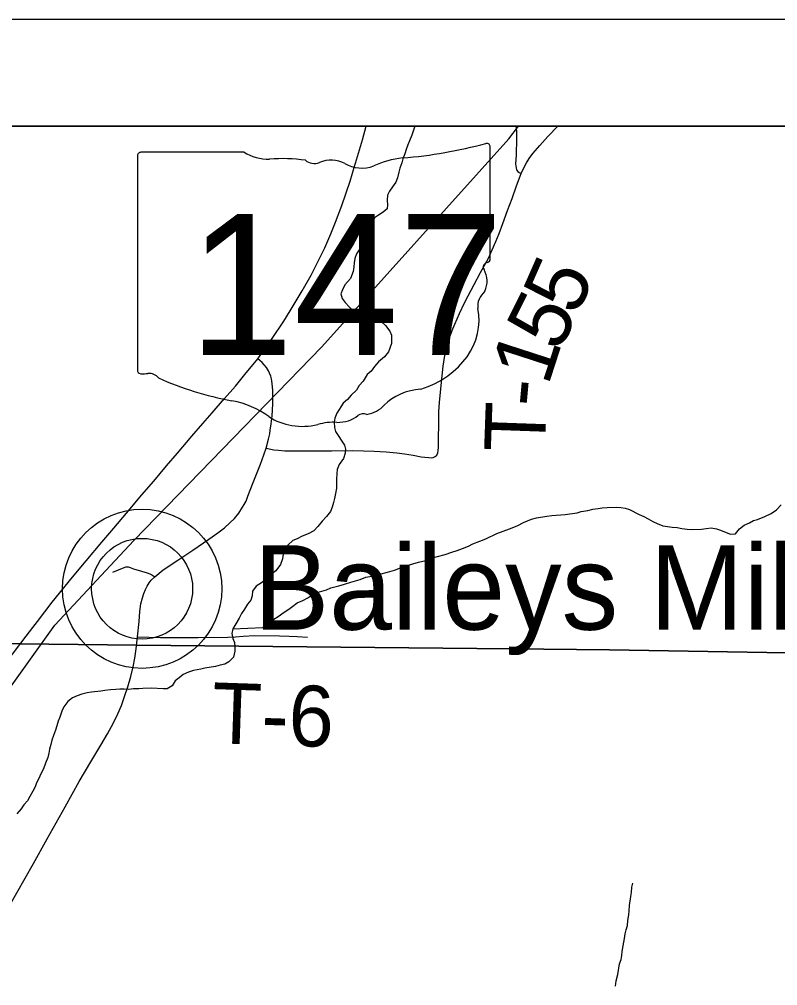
# Model space of a CAD drawing. Extents: x 0 to 34, y 0 to 22.
# Drawn here: x 27.124 to 27.832, y 20.097 to 21 of the extents above; entities that cross this region are included whole.
import ezdxf

# ---------------------------------------------------------------- set-up
doc = ezdxf.new("R2010")
doc.units = 0
for name, color, linetype in [('GM_X_Corporation', 7, 'Continuous'), ('GM_X_Minor_River', 7, 'Continuous'), ('GM_X_Rail_Line', 7, 'Continuous'), ('GM_X_State_Route', 7, 'Continuous'), ('GM_X_State_Shield', 7, 'Continuous'), ('GM_X_Township_Road', 7, 'Continuous'), ('GM_X_Township_Road_Text', 7, 'Continuous'), ('GM_X_Unincorporated', 7, 'Continuous'), ('GM_X_Unincorporated_Location', 7, 'Continuous'), ('GM_X_Unincorporated_Text', 7, 'Continuous'), ('SH_Data', 7, 'Continuous')]:
    doc.layers.add(name, color=color, linetype=linetype)

msp = doc.modelspace()

# ---------------------------------------------------------------- linework, layer by layer
at = {"layer": 'GM_X_Corporation'}
for points in [[(30.31667, 20.9), (27.1022, 20.9), (27.08976, 20.41697), (27.08968, 20.41348), (27.08896, 20.36917), (27.08729, 20.26647), (27.09073, 20.12299), (27.08852, 20.11389), (27.08642, 20.01381), (27.07613, 19.68064), (27.07326, 19.49798), (27.07194, 19.39116), (27.04874, 18.58046), (27.04191, 17.82361), (27.03491, 17.55216), (27.02338, 16.66109), (27.01239, 14.98802), (27.00568, 14.51357), (27.29989, 14.51067), (27.80309, 14.50906), (28.4032, 14.497)], [(29.55027, 20.37882), (27.67509, 20.4106), (27.58291, 20.41163), (27.2336, 20.4152), (27.12389, 20.41631), (27.08976, 20.41697), (27.08968, 20.41348), (27.08896, 20.36917), (27.08729, 20.26647), (27.09073, 20.12299), (27.08852, 20.11389), (27.08642, 20.01381), (27.07613, 19.68064), (27.07326, 19.49798), (27.07194, 19.39116), (27.04874, 18.58046), (27.04191, 17.82361), (27.03491, 17.55216), (27.02338, 16.66109), (27.01239, 14.98802), (27.00568, 14.51357), (27.29989, 14.51067), (27.80309, 14.50906), (28.4032, 14.497)]]:
    msp.add_lwpolyline(points, dxfattribs=at)
msp.add_lwpolyline([(30.31667, 20.36493), (30.31667, 20.9), (27.1022, 20.9), (27.08976, 20.41697), (27.12389, 20.41631), (27.2336, 20.4152), (27.58291, 20.41163), (27.67509, 20.4106), (29.55027, 20.37882)], close=True, dxfattribs=at)
at = {"layer": 'GM_X_Minor_River'}
msp.add_line((27.49339, 20.9), (27.49271, 20.89826), dxfattribs=at)
for points in [[(27.49271, 20.89826), (27.49055, 20.89178), (27.48837, 20.88644), (27.48692, 20.88262), (27.4851, 20.87842), (27.48404, 20.87423), (27.48223, 20.86964), (27.48116, 20.86584), (27.47935, 20.86088), (27.47828, 20.85707), (27.47724, 20.85174), (27.47542, 20.84792), (27.47247, 20.84331), (27.46951, 20.83947), (27.46768, 20.83565), (27.46738, 20.83109), (27.46784, 20.82655), (27.46753, 20.82275), (27.4638, 20.81965), (27.45931, 20.81692), (27.45556, 20.81458), (27.45298, 20.81075), (27.45191, 20.80693), (27.45047, 20.80274), (27.45056, 20.79781), (27.44988, 20.79325), (27.44616, 20.78977), (27.44207, 20.78553), (27.43874, 20.78092), (27.43731, 20.77635), (27.43662, 20.77254), (27.43631, 20.76875), (27.43563, 20.76418), (27.43309, 20.75769), (27.42789, 20.75192), (27.4257, 20.74733), (27.42426, 20.74351), (27.42547, 20.73898), (27.42818, 20.73524), (27.43628, 20.72666), (27.44049, 20.72408), (27.44505, 20.72264), (27.44885, 20.72157), (27.4538, 20.72014), (27.45837, 20.71832), (27.46217, 20.71725), (27.46602, 20.71391), (27.46989, 20.70867), (27.47147, 20.7049), (27.47161, 20.69694), (27.46872, 20.68931), (27.46501, 20.68469), (27.45942, 20.68004), (27.45571, 20.67543), (27.45238, 20.6712), (27.44865, 20.6681), (27.44497, 20.66197), (27.44126, 20.65774), (27.43869, 20.65352), (27.43385, 20.64888), (27.43052, 20.64465), (27.42642, 20.64117), (27.42052, 20.63197), (27.41871, 20.62738), (27.41802, 20.62358), (27.4181, 20.61865), (27.41931, 20.61488), (27.42164, 20.61113), (27.42514, 20.60588), (27.42747, 20.60213), (27.42867, 20.59836), (27.42836, 20.59456), (27.42656, 20.5896), (27.4225, 20.58384), (27.42068, 20.57926), (27.42037, 20.57546), (27.42009, 20.56977), (27.42023, 20.56181), (27.41918, 20.55686), (27.41813, 20.55229), (27.41744, 20.54849), (27.416, 20.54391), (27.41456, 20.5401), (27.41085, 20.53548), (27.40677, 20.53086), (27.40269, 20.52586), (27.39898, 20.522), (27.39373, 20.51925), (27.38809, 20.51688), (27.38322, 20.51452), (27.37946, 20.51294), (27.37461, 20.50868), (27.37205, 20.50408), (27.37022, 20.50026), (27.36954, 20.4957), (27.36774, 20.49036), (27.3633, 20.48459), (27.35845, 20.48071), (27.35473, 20.47686), (27.34988, 20.47336), (27.34501, 20.47024)], [(27.32338, 20.43042), (27.35136, 20.43167), (27.35658, 20.43593), (27.3607, 20.43866), (27.36669, 20.44256), (27.37042, 20.44528), (27.37566, 20.44878), (27.3794, 20.4515), (27.3835, 20.45461), (27.38876, 20.45697), (27.39326, 20.45933), (27.4, 20.46362), (27.40639, 20.46563), (27.41092, 20.46684), (27.41467, 20.46881), (27.4222, 20.47045), (27.42747, 20.47206), (27.43349, 20.47406), (27.44215, 20.47649), (27.44742, 20.47848), (27.45307, 20.47972), (27.45683, 20.48092), (27.46061, 20.48137), (27.46776, 20.48339), (27.47417, 20.48502), (27.4783, 20.48661), (27.48206, 20.48819), (27.4862, 20.4894), (27.49674, 20.49262), (27.50352, 20.49425), (27.50992, 20.49664), (27.51443, 20.49786), (27.52159, 20.49988), (27.52799, 20.50189), (27.53288, 20.50349), (27.53776, 20.50547), (27.54341, 20.50746), (27.54753, 20.50981), (27.55392, 20.5122), (27.55955, 20.51457), (27.57006, 20.51931), (27.5757, 20.52168), (27.58172, 20.52368), (27.58585, 20.52527), (27.58961, 20.52686), (27.59486, 20.5296), (27.60237, 20.53277), (27.60689, 20.53398), (27.6167, 20.53567), (27.62124, 20.53613), (27.63371, 20.53711), (27.64503, 20.53882), (27.64879, 20.54003), (27.65483, 20.54089), (27.65973, 20.54211), (27.66463, 20.54296), (27.66841, 20.54341), (27.67294, 20.54386), (27.68202, 20.54402), (27.68581, 20.54371), (27.68999, 20.54303), (27.69379, 20.54196), (27.70295, 20.53719), (27.70715, 20.53536), (27.71135, 20.53316), (27.71556, 20.53058), (27.71975, 20.52876), (27.72509, 20.52657), (27.72926, 20.52589), (27.73381, 20.52521), (27.73836, 20.52491), (27.74291, 20.52423), (27.74784, 20.52356), (27.75163, 20.52325), (27.76109, 20.52341), (27.76562, 20.52425), (27.77015, 20.52471), (27.77509, 20.52366), (27.77889, 20.52259), (27.78423, 20.52041), (27.78842, 20.51896), (27.79295, 20.51904), (27.79666, 20.52366), (27.80114, 20.52715), (27.80602, 20.52951), (27.80977, 20.53147), (27.81353, 20.53268), (27.82029, 20.53545), (27.8263, 20.53821), (27.83116, 20.54171), (27.83562, 20.54634)], [(27.34501, 20.47024), (27.34169, 20.46563), (27.34139, 20.46107), (27.33994, 20.45726), (27.33698, 20.45341), (27.33403, 20.44881), (27.33146, 20.44459), (27.32926, 20.44038), (27.32595, 20.43502), (27.32338, 20.43042), (27.32233, 20.42585), (27.32316, 20.42132), (27.32474, 20.41755), (27.32519, 20.41339), (27.32526, 20.40959), (27.32384, 20.40388), (27.31938, 20.39963), (27.31563, 20.39729), (27.31149, 20.39646), (27.30697, 20.39524), (27.29716, 20.39355), (27.29339, 20.39273), (27.2866, 20.39147), (27.28171, 20.38987), (27.27683, 20.38751), (27.2731, 20.38441), (27.26936, 20.38169), (27.26642, 20.37709), (27.26192, 20.37435), (27.25814, 20.37428), (27.24716, 20.37485), (27.23921, 20.37471), (27.23544, 20.37427), (27.23052, 20.37418), (27.22599, 20.37372), (27.22182, 20.37403), (27.21766, 20.37396), (27.21388, 20.37351), (27.20896, 20.37342), (27.20368, 20.37257), (27.1999, 20.37213), (27.19122, 20.37122), (27.18707, 20.37039), (27.18217, 20.36916), (27.17766, 20.36757), (27.17352, 20.36598), (27.16904, 20.36249), (27.16535, 20.35749), (27.16353, 20.35329), (27.16173, 20.34794), (27.1599, 20.34412), (27.15885, 20.33955), (27.1574, 20.33573), (27.1556, 20.33077), (27.15416, 20.32619), (27.1531, 20.32238), (27.15204, 20.31781), (27.15135, 20.31401), (27.15028, 20.3102), (27.1481, 20.30485), (27.14631, 20.29951), (27.14374, 20.29491), (27.14192, 20.29033), (27.13972, 20.2865), (27.13865, 20.28269), (27.13646, 20.27847), (27.13352, 20.27349), (27.13131, 20.26966), (27.12798, 20.26581), (27.12539, 20.26197), (27.12131, 20.25735)], [(27.68078, 20.09646), (27.68145, 20.1014), (27.68286, 20.10712), (27.68457, 20.11739), (27.68602, 20.12121), (27.68671, 20.12501), (27.68702, 20.12881), (27.68806, 20.13414), (27.68908, 20.14099), (27.68976, 20.14517), (27.69083, 20.14898), (27.69189, 20.15318), (27.69219, 20.15773), (27.69323, 20.16306), (27.69354, 20.16686), (27.69383, 20.1718), (27.6952, 20.18017), (27.69589, 20.18397), (27.69618, 20.18891), (27.69687, 20.19271)]]:
    msp.add_lwpolyline(points, dxfattribs=at)
at = {"layer": 'GM_X_Rail_Line'}
msp.add_lwpolyline([(27.09617, 20.34866), (27.10321, 20.35936), (27.15695, 20.43382), (27.23063, 20.51302), (27.40626, 20.69391), (27.58107, 20.88831), (27.59007, 20.9)], dxfattribs=at)
at = {"layer": 'GM_X_State_Route'}
for points in [[(27.43732, 20.86361), (27.43789, 20.86547), (27.44432, 20.88745), (27.44797, 20.9)], [(27.34647, 20.68274), (27.35389, 20.69305), (27.36001, 20.70157), (27.37088, 20.71799), (27.37692, 20.72767), (27.38246, 20.73677), (27.38809, 20.74639), (27.39631, 20.76094), (27.40339, 20.77467), (27.40906, 20.7865), (27.41473, 20.79958), (27.41917, 20.81051), (27.425, 20.82605), (27.43273, 20.84873), (27.43732, 20.86361)], [(27.13029, 20.42355), (27.13332, 20.42759), (27.13644, 20.43174), (27.1406, 20.43719), (27.15448, 20.45541), (27.17333, 20.47878), (27.18612, 20.49393), (27.20073, 20.51125), (27.21192, 20.52444), (27.2238, 20.53845), (27.23836, 20.5556), (27.24935, 20.56849), (27.26132, 20.58256), (27.27151, 20.59452), (27.28497, 20.61045), (27.29521, 20.6222), (27.30404, 20.63232), (27.31551, 20.64548), (27.32581, 20.65729), (27.33459, 20.66811), (27.34647, 20.68274)], [(27.2342, 20.42271), (27.23561, 20.43723), (27.23635, 20.44652), (27.23738, 20.45362), (27.23873, 20.45939), (27.23998, 20.46334), (27.24152, 20.467), (27.24309, 20.47011), (27.24498, 20.47323), (27.24704, 20.47578), (27.25024, 20.47907), (27.25822, 20.48548), (27.27178, 20.49452), (27.28602, 20.50384), (27.30082, 20.51402), (27.30936, 20.52001), (27.31541, 20.52483), (27.32036, 20.52926), (27.3247, 20.53355), (27.32872, 20.53846), (27.33243, 20.5439), (27.33391, 20.54646), (27.33559, 20.54977), (27.33737, 20.5542), (27.34238, 20.56707), (27.34905, 20.58429), (27.35217, 20.59292), (27.35431, 20.59908), (27.35653, 20.60747), (27.35768, 20.61248), (27.35826, 20.61594), (27.35916, 20.62185), (27.3599, 20.62933), (27.36047, 20.64043), (27.36056, 20.65301), (27.36015, 20.65975), (27.35941, 20.66386), (27.35867, 20.66657), (27.3576, 20.66929), (27.35653, 20.67151), (27.35464, 20.67454), (27.35241, 20.67704), (27.35054, 20.67918), (27.34845, 20.68113), (27.34647, 20.68274)], [(27.08916, 20.36864), (27.10781, 20.39383), (27.11722, 20.40659), (27.13029, 20.42355)], [(27.0915, 20.12452), (27.09179, 20.12556), (27.09344, 20.1305), (27.09585, 20.13638), (27.09826, 20.14187), (27.10076, 20.14697), (27.11368, 20.16992), (27.13686, 20.21109), (27.14967, 20.2342), (27.16661, 20.26404), (27.17961, 20.28754), (27.19059, 20.30612), (27.20002, 20.32162), (27.20628, 20.33231), (27.21177, 20.34242), (27.21571, 20.35079), (27.21909, 20.35859), (27.22217, 20.36706), (27.22515, 20.37611), (27.22794, 20.38593), (27.23006, 20.39488), (27.2317, 20.40297), (27.23304, 20.41154), (27.2342, 20.42271)]]:
    msp.add_lwpolyline(points, dxfattribs=at)
at = {"layer": 'GM_X_State_Shield'}
for p, q in [((27.23412, 20.87233), (27.23412, 20.67221)), ((27.33389, 20.87577), (27.23737, 20.87577)), ((27.56371, 20.77605), (27.56371, 20.88073)), ((27.56367, 20.77607), (27.56371, 20.77605))]:
    msp.add_line(p, q, dxfattribs=at)
for centre, major_axis, start_param, end_param in [((27.4463, 21.1486), (0.34952, 0), 4.814394, 5.042369), ((27.56005, 20.88117), (0.00367, 0), 6.141152, 7.989035), ((27.2379, 20.87275), (0.00382, 0), 1.712693, 3.28349), ((27.35687, 20.899), (0.03703, 0), 4.042523, 4.731795), ((27.36915, 20.76342), (0.13295, 0), 1.404758, 1.657858), ((27.39934, 20.87379), (0.01068, 0), 3.836095, 5.185415), ((27.41502, 20.85066), (0.02221, 0), 0.950623, 2.079405), ((27.44369, 20.88239), (0.02672, 0), 4.081561, 5.145723), ((27.49089, 20.81465), (0.07032, 0), 1.699011, 2.107814), ((27.55979, 20.77564), (0.00393, 0), 5.05454, 6.418171), ((27.56286, 20.76836), (0.00568, 0), 1.883978, 3.671073), ((27.52673, 20.75513), (0.03409, 0), 5.934695, 6.695948), ((27.57685, 20.73224), (0.0248, 0), 2.387724, 3.262537), ((27.46588, 20.71892), (0.08742, 0), 5.101752, 6.440018), ((27.23793, 20.67177), (0.00385, 0), 3.00124, 4.508301), ((27.23852, 20.69224), (0.0294, 0), 4.665946, 4.897461), ((27.24453, 20.66066), (0.0106, 0), 0.519207, 1.627899), ((27.37836, 20.84046), (0.2524, 0), 4.195997, 4.488961), ((27.50274, 20.61602), (0.04788, 0), 1.647645, 2.488434), ((27.30311, 20.5823), (0.07897, 0), 0.823519, 1.323587), ((27.44208, 20.65281), (0.02824, 0), 4.937069, 5.64225), ((27.38852, 20.65967), (0.05011, 0), 4.026481, 4.996735), ((27.42113, 20.64468), (0.0267, 0), 4.691044, 5.507374), ((27.44529, 20.6253), (0.00752, 0), 1.147584, 2.315152), ((27.41747, 20.59048), (0.04118, 0), 1.495662, 1.94098)]:
    msp.add_ellipse(centre, major_axis=major_axis, ratio=0.8, start_param=start_param, end_param=end_param, dxfattribs=at)
at = {"layer": 'GM_X_Township_Road'}
for points in [[(27.58778, 20.9), (27.58821, 20.89562), (27.58846, 20.88853), (27.58813, 20.87312), (27.5875, 20.86492), (27.58762, 20.86301), (27.58791, 20.86113), (27.58839, 20.85928), (27.58943, 20.85792), (27.59079, 20.85684), (27.59267, 20.85592)], [(27.59267, 20.85592), (27.5943, 20.85942), (27.59766, 20.86593), (27.60018, 20.86998), (27.6037, 20.87469), (27.61018, 20.882), (27.61767, 20.89039), (27.62699, 20.9)], [(27.51237, 20.59131), (27.51377, 20.59271), (27.51475, 20.59469), (27.51524, 20.59682), (27.51549, 20.60019), (27.51568, 20.62964), (27.51582, 20.63346), (27.51637, 20.64201), (27.51762, 20.65474), (27.51881, 20.66676), (27.51986, 20.67575), (27.52116, 20.6839), (27.52255, 20.69066), (27.52424, 20.69735), (27.52576, 20.70226), (27.52723, 20.70661), (27.52883, 20.71065), (27.53065, 20.71503), (27.5349, 20.72502), (27.53963, 20.73492), (27.54313, 20.74156), (27.54881, 20.75218), (27.55481, 20.76339), (27.56203, 20.77689), (27.5657, 20.78447), (27.5691, 20.79227), (27.57209, 20.79996), (27.57549, 20.80919), (27.57994, 20.82129), (27.58412, 20.83268), (27.58846, 20.84447), (27.59267, 20.85592)], [(27.35431, 20.59908), (27.36163, 20.59769), (27.36607, 20.5972), (27.37199, 20.59678), (27.39762, 20.59666), (27.41537, 20.59681), (27.43551, 20.59698), (27.45524, 20.59649), (27.46642, 20.59584), (27.47634, 20.59491), (27.48357, 20.59396), (27.49181, 20.59254), (27.49938, 20.59123), (27.50276, 20.59074), (27.50653, 20.59033), (27.50884, 20.59024), (27.51056, 20.59049), (27.51237, 20.59131)], [(27.21115, 20.48335), (27.22157, 20.48773), (27.22333, 20.48829), (27.2253, 20.48836), (27.22741, 20.48773), (27.23046, 20.48657), (27.2378, 20.48425), (27.24308, 20.48258), (27.24563, 20.48176), (27.24755, 20.48082), (27.25024, 20.47907)], [(27.2342, 20.42271), (27.25567, 20.42234), (27.27133, 20.42223), (27.29084, 20.42212), (27.31868, 20.42246), (27.32572, 20.42288), (27.33287, 20.42345), (27.34388, 20.42411), (27.36692, 20.42392), (27.37592, 20.42355), (27.38341, 20.42326), (27.3931, 20.4226)]]:
    msp.add_lwpolyline(points, dxfattribs=at)
at = {"layer": 'GM_X_Unincorporated'}
for radius in [0.0744, 0.04716]:
    msp.add_circle((27.2385, 20.46776), radius, dxfattribs=at)
at = {"layer": 'GM_X_Unincorporated_Location'}
msp.add_line((27.2385, 20.46776), (27.2385, 20.46776), dxfattribs=at)
at = {"layer": 'SH_Data'}
for points in [[(23.41667, 21), (30.41667, 21), (30.41667, 14), (23.41667, 14)], [(23.51667, 20.9), (30.31667, 20.9), (30.31667, 14.1), (23.51667, 14.1)]]:
    msp.add_lwpolyline(points, close=True, dxfattribs=at)

# ---------------------------------------------------------------- texts
at = {"layer": 'GM_X_State_Shield'}
msp.add_text('147', height=0.131836, dxfattribs=at).set_placement((27.28198, 20.68632))
at = {"layer": 'GM_X_Township_Road_Text'}
for s, height, rotation, p in [('5', 0.05682, 66.23076, (27.64457, 20.72174)), ('5', 0.05682, 63.46985, (27.62767, 20.68772)), ('1', 0.05682, 72.00115, (27.6177, 20.6565)), ('-', 0.05682, 84.76245, (27.61624, 20.63654)), ('T', 0.05682, 87.98961, (27.6148, 20.59491)), ('T-6', 0.056818, 358.09194, (27.30291, 20.32354))]:
    msp.add_text(s, height=height, rotation=rotation, dxfattribs=at).set_placement(p)
at = {"layer": 'GM_X_Unincorporated_Text'}
msp.add_text('Baileys Mills', height=0.0789773, rotation=0.00001, dxfattribs=at).set_placement((27.34286, 20.42956))

doc.saveas('drawing.dxf')
